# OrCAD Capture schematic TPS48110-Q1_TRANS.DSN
size B; title: TPS48110-Q1: 100-V Smart High Side Driver with Protection; rev: 1.0; note: Datasheet: SLUSEE5     EVM: TPS48110Q1EVM; note: and Diagnostics
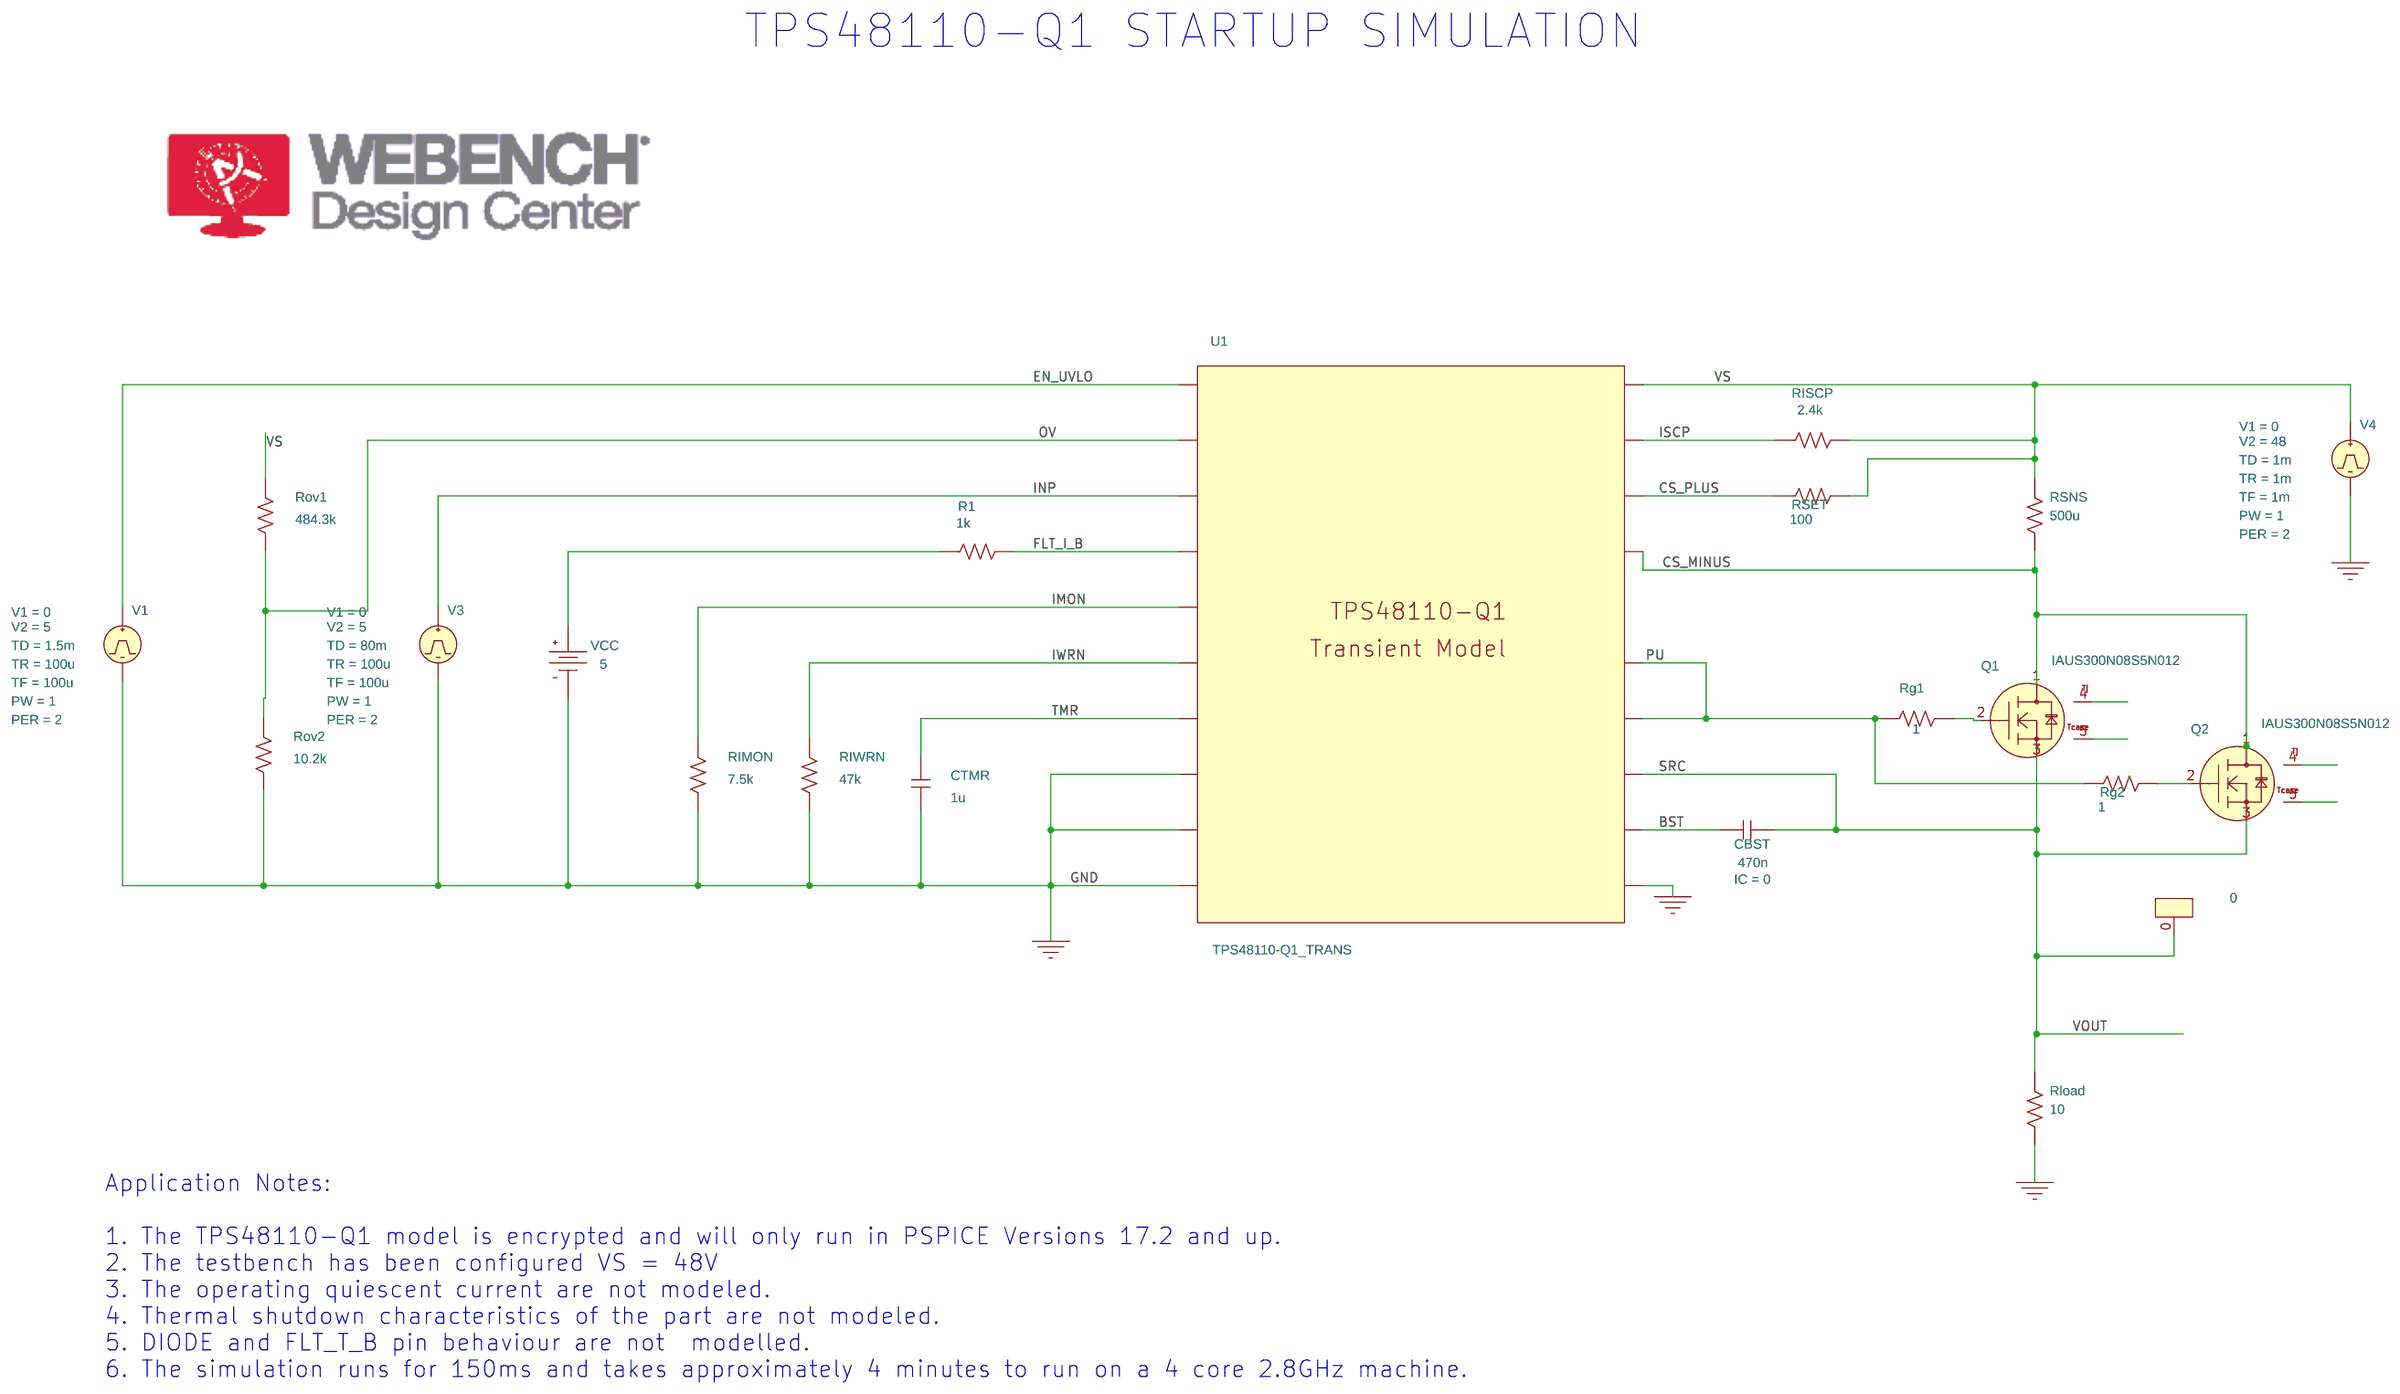
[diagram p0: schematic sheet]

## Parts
CBST  470n  [RAD/CK05]
CTMR  1u  [RAD/CK05]
IC1  0
Q1  IAUS300N08S5N012
Q2  IAUS300N08S5N012
R1  1k  [AX/RC05]
Rg1  1  [AX/RC05]
Rg2  1  [AX/RC05]
RIMON  7.5k  [AX/RC05]
RISCP  2.4k  [AX/RC05]
RIWRN  47k  [AX/RC05]
Rload  10  [AX/RC05]
Rov1  484.3k  [AX/RC05]
Rov2  10.2k  [AX/RC05]
RSET  100  [AX/RC05]
RSNS  500u  [AX/RC05]
U1  TPS48110-Q1_TRANS
V1  VPULSE
V3  VPULSE
V4  VPULSE
VCC  VDC

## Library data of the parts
CBST = C: IC: 0
CTMR = C
IC1 = IC1
Q1 Q2 = IAUS300N08S5N012
R1 Rg1 Rg2 RIMON RISCP RIWRN Rload Rov1 Rov2 RSET RSNS = R
U1 = TPS48110-Q1_TRANS: PSpiceTemplate: X^@REFDES  %BST %CS_MINUS %CS_PLUS %DIODE %EN_UVLO %FLT_I_B %FLT_T_B %GND %IMON %INP %ISCP %IWRN %NC %OV %PD %PU %SRC %TMR %VS @MODEL
V1 = VPULSE: PER: 2; PW: 1; TD: 1.5m; TF: 100u; TR: 100u; V1: 0; V2: 5
V3 = VPULSE: PER: 2; PW: 1; TD: 80m; TF: 100u; TR: 100u; V1: 0; V2: 5
V4 = VPULSE: PER: 2; PW: 1; TD: 1m; TF: 1m; TR: 1m; V1: 0; V2: 48
VCC = VDC: DC: 5

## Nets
0: CTMR.2 RIMON.2 RIWRN.2 Rload.2 Rov2.2 U1.DIODE U1.FLT_T_B U1.GND U1.NC V1.2(-) V3.2(-) V4.2(-) VCC.1(-)
BST: CBST.1 U1.BST
CS_MINUS: Q1.1(drain) Q2.1(drain) RSNS.2 U1.CS_MINUS
CS_PLUS: RSET.1 U1.CS_PLUS
EN_UVLO: U1.EN_UVLO V1.1(+)
FLT_I_B: R1.2 U1.FLT_I_B
IMON: RIMON.1 U1.IMON
INP: U1.INP V3.1(+)
ISCP: RISCP.1 U1.ISCP
IWRN: RIWRN.1 U1.IWRN
OV: Rov1.2 Rov2.1 U1.OV
PU: Rg1.2 Rg2.1 U1.PD U1.PU
SRC: CBST.2 IC1.0(+) Q1.3(source) Q2.3(source) Rload.1 U1.SRC
TMR: CTMR.1 U1.TMR
VS: RISCP.2 Rov1.1 RSET.2 RSNS.1 U1.VS V4.1(+)
N16579999: R1.1 VCC.0(+)
N16772823: Q1.2(gate) Rg1.1
N16773005: Q2.2(gate) Rg2.2

Not connected (* = marked no-connect by the designer): Q1 4(Tj) 5(Tcase); Q2 4(Tj) 5(Tcase)

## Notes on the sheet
- TPS48110-Q1 STARTUP SIMULATION
- Application Notes:
  1. The TPS48110-Q1 model is encrypted and will only run in PSPICE Versions 17.2 and up.
  2. The testbench has been configured VS = 48V
  3. The operating quiescent current are not modeled.
  4. Thermal shutdown characteristics of the part are not modeled.
  5. DIODE and FLT_T_B pin behaviour are not  modelled.
  6. The simulation runs for 150ms and takes approximately 4 minutes to run on a 4 core 2.8GHz machine.
